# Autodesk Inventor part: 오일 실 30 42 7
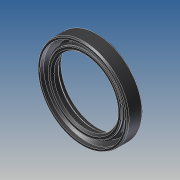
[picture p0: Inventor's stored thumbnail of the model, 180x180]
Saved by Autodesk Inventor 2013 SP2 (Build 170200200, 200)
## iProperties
Created: 2025-06
Part Number: 오일 실 30 42 7
Material: Generic
Document SubType Name: Modeling
Designer: i
Density: 1 g/cm^3
Author: i
변환 표준: STEP AP214IS
전처리기: Build: 200, Release: 2013 SP2 Update 6 - Date: Thu 07/17/2014
전송 단위: 밀리미터
불확실성: 0.01
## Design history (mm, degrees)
node "오일 실 30 42 71"
body "Solid1"
node "기준1"
